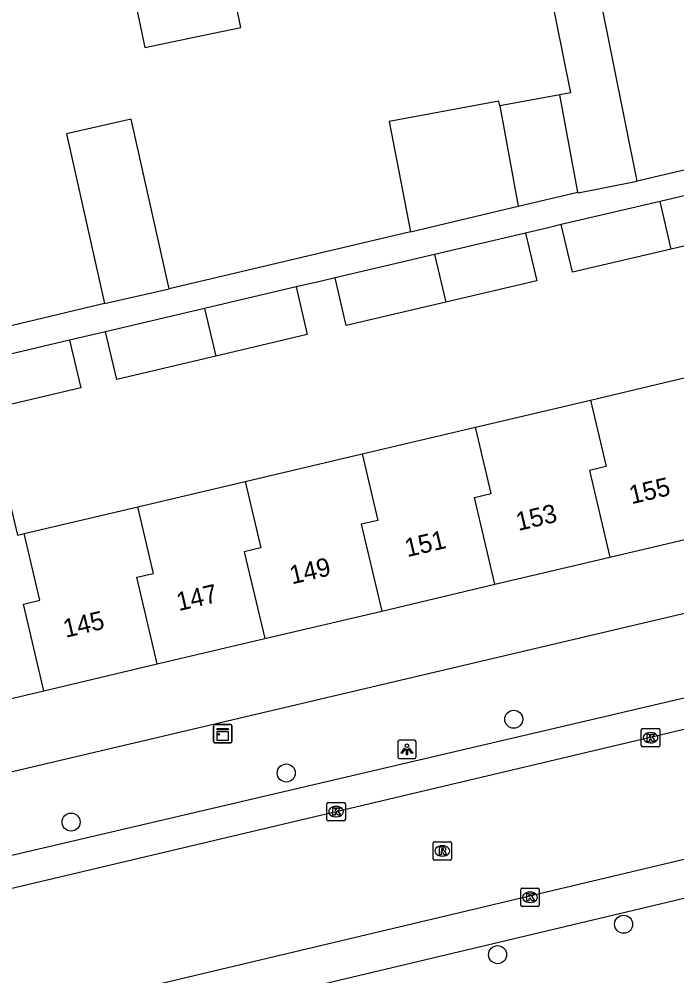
# Model space of a CAD drawing. Extents: x 162990 to 165007, y 383433 to 384336.
# Drawn here: x 164173.2 to 164208.8, y 384114.3 to 384166.2 of the extents above; entities that cross this region are included whole.
import ezdxf

# ---------------------------------------------------------------- set-up
doc = ezdxf.new("R2010")
doc.units = 0
for name, color, linetype in [('IMGEO_Boom', 7, 'Continuous'), ('IMGEO_Kast', 7, 'Continuous'), ('IMGEO_Kolk', 7, 'Continuous'), ('IMGEO_Lichtpunt', 7, 'Continuous'), ('IMGEO_Pand', 7, 'Continuous'), ('IMGEO_Pand_nummerreeks', 7, 'Continuous'), ('IMGEO_Rijbaan_lokaal_open', 7, 'Continuous'), ('IMGEO_Rioolput', 7, 'Continuous'), ('IMGEO_Voetpad_open', 7, 'Continuous')]:
    doc.layers.add(name, color=color, linetype=linetype)

msp = doc.modelspace()

# ---------------------------------------------------------------- linework, layer by layer
at = {"layer": 'IMGEO_Boom'}
for centre in [(164199.955, 384128.23), (164187.625, 384125.313), (164175.968, 384122.65), (164205.906, 384117.115), (164199.074, 384115.466)]:
    msp.add_circle(centre, 0.489, dxfattribs=at)
at = {"layer": 'IMGEO_Kast'}
for p, q in [((164183.687, 384127.02), (164183.687, 384127.861)), ((164183.687, 384127.861), (164183.687, 384127.02)), ((164183.762, 384127.945), (164184.603, 384127.945)), ((164184.603, 384127.945), (164183.762, 384127.945)), ((164184.687, 384127.87), (164184.687, 384127.029)), ((164184.687, 384127.029), (164184.687, 384127.87)), ((164184.612, 384126.945), (164183.771, 384126.945)), ((164183.771, 384126.945), (164184.612, 384126.945))]:
    msp.add_line(p, q, dxfattribs=at)
for points in [[(164183.882, 384127.735), (164184.482, 384127.735), (164184.482, 384127.65), (164183.882, 384127.65), (164183.882, 384127.735)], [(164183.882, 384127.56), (164184.482, 384127.56), (164184.482, 384127.071), (164183.882, 384127.071), (164183.882, 384127.56)]]:
    msp.add_lwpolyline(points, dxfattribs=at)
msp.add_circle((164183.966, 384127.409), 0.0377, dxfattribs=at)
for centre, start, end in [((164183.765, 384127.867), 92.4484, 184.2845), ((164183.765, 384127.867), 92.4484, 184.2845), ((164184.609, 384127.867), 2.4484, 94.2845), ((164184.609, 384127.867), 2.4484, 94.2845), ((164183.765, 384127.023), 182.4484, 274.2845), ((164183.765, 384127.023), 182.4484, 274.2845), ((164184.609, 384127.023), 272.4484, 4.2845), ((164184.609, 384127.023), 272.4484, 4.2845)]:
    msp.add_arc(centre, 0.0779, start, end, dxfattribs=at)
at = {"layer": 'IMGEO_Kolk'}
for p, q in [((164206.938, 384127.728), (164207.79, 384127.728)), ((164206.863, 384126.802), (164206.863, 384127.654)), ((164207.351, 384127.508), (164207.376, 384127.508)), ((164207.864, 384127.654), (164207.864, 384126.802)), ((164207.79, 384126.728), (164206.938, 384126.728)), ((164207.374, 384126.948), (164207.349, 384126.948)), ((164189.828, 384122.795), (164189.828, 384123.647)), ((164189.903, 384123.721), (164190.755, 384123.721)), ((164190.829, 384123.647), (164190.829, 384122.795)), ((164190.316, 384123.501), (164190.341, 384123.501)), ((164190.755, 384122.721), (164189.903, 384122.721)), ((164190.339, 384122.941), (164190.314, 384122.941)), ((164200.335, 384118.15), (164200.335, 384119.002)), ((164200.41, 384119.076), (164201.262, 384119.076)), ((164201.336, 384119.002), (164201.336, 384118.15)), ((164200.823, 384118.856), (164200.848, 384118.856)), ((164201.262, 384118.076), (164200.41, 384118.076)), ((164200.846, 384118.296), (164200.821, 384118.296))]:
    msp.add_line(p, q, dxfattribs=at)
for points in [[(164206.938, 384127.728), (164207.79, 384127.728)], [(164206.863, 384126.802), (164206.863, 384127.654)], [(164207.184, 384127.428), (164207.307, 384127.428), (164207.307, 384127.277), (164207.437, 384127.428), (164207.601, 384127.428), (164207.455, 384127.277), (164207.608, 384127.028), (164207.456, 384127.028), (164207.371, 384127.192), (164207.307, 384127.125), (164207.307, 384127.028), (164207.184, 384127.028), (164207.184, 384127.428)], [(164207.864, 384127.654), (164207.864, 384126.802)], [(164207.79, 384126.728), (164206.938, 384126.728)], [(164189.828, 384122.795), (164189.828, 384123.647)], [(164189.903, 384123.721), (164190.755, 384123.721)], [(164190.829, 384123.647), (164190.829, 384122.795)], [(164190.149, 384123.421), (164190.272, 384123.421), (164190.272, 384123.27), (164190.402, 384123.421), (164190.566, 384123.421), (164190.42, 384123.27), (164190.573, 384123.021), (164190.421, 384123.021), (164190.336, 384123.185), (164190.272, 384123.118), (164190.272, 384123.021), (164190.149, 384123.021), (164190.149, 384123.421)], [(164190.755, 384122.721), (164189.903, 384122.721)], [(164200.335, 384118.15), (164200.335, 384119.002)], [(164200.41, 384119.076), (164201.262, 384119.076)], [(164201.336, 384119.002), (164201.336, 384118.15)], [(164200.656, 384118.776), (164200.779, 384118.776), (164200.779, 384118.625), (164200.909, 384118.776), (164201.073, 384118.776), (164200.927, 384118.625), (164201.08, 384118.376), (164200.928, 384118.376), (164200.843, 384118.54), (164200.779, 384118.473), (164200.779, 384118.376), (164200.656, 384118.376), (164200.656, 384118.776)], [(164201.262, 384118.076), (164200.41, 384118.076)]]:
    msp.add_lwpolyline(points, dxfattribs=at)
for centre, start, end in [((164206.94, 384127.652), 91.552, 178.448), ((164206.94, 384127.652), 91.552, 178.448), ((164207.788, 384127.652), 1.552, 88.448), ((164207.788, 384127.652), 1.552, 88.448), ((164206.94, 384126.804), 181.552, 268.448), ((164206.94, 384126.804), 181.552, 268.448), ((164207.788, 384126.804), 271.552, 358.448), ((164207.788, 384126.804), 271.552, 358.448), ((164189.905, 384123.645), 91.552, 178.448), ((164189.905, 384123.645), 91.552, 178.448), ((164190.753, 384123.645), 1.552, 88.448), ((164190.753, 384123.645), 1.552, 88.448), ((164189.905, 384122.797), 181.552, 268.448), ((164189.905, 384122.797), 181.552, 268.448), ((164190.753, 384122.797), 271.552, 358.448), ((164190.753, 384122.797), 271.552, 358.448), ((164200.412, 384119), 91.552, 178.448), ((164200.412, 384119), 91.552, 178.448), ((164201.26, 384119), 1.552, 88.448), ((164201.26, 384119), 1.552, 88.448), ((164200.412, 384118.152), 181.552, 268.448), ((164200.412, 384118.152), 181.552, 268.448), ((164201.26, 384118.152), 271.552, 358.448), ((164201.26, 384118.152), 271.552, 358.448)]:
    msp.add_arc(centre, 0.0765, start, end, dxfattribs=at)
for centre, major_axis, ratio, start_param, end_param in [((164207.35, 384127.228), (-0.387, 0.002), 0.722429, 4.712389, 7.853982), ((164207.375, 384127.228), (-0.39, 0.002), 0.717154, 1.570796, 4.712389), ((164190.315, 384123.221), (-0.387, 0.002), 0.722429, 4.712389, 7.853982), ((164190.34, 384123.221), (-0.39, 0.002), 0.717154, 1.570796, 4.712389), ((164200.822, 384118.576), (-0.387, 0.002), 0.722429, 4.712389, 7.853982), ((164200.847, 384118.576), (-0.39, 0.002), 0.717154, 1.570796, 4.712389)]:
    msp.add_ellipse(centre, major_axis=major_axis, ratio=ratio, start_param=start_param, end_param=end_param, dxfattribs=at)
at = {"layer": 'IMGEO_Lichtpunt'}
for p, q in [((164193.667, 384126.997), (164193.667, 384126.19)), ((164193.667, 384126.997), (164193.667, 384126.19)), ((164194.569, 384127.092), (164193.761, 384127.092)), ((164194.569, 384127.092), (164193.761, 384127.092)), ((164194.663, 384126.19), (164194.663, 384126.997)), ((164194.663, 384126.19), (164194.663, 384126.997)), ((164193.761, 384126.096), (164194.569, 384126.096)), ((164193.761, 384126.096), (164194.569, 384126.096))]:
    msp.add_line(p, q, dxfattribs=at)
for points in [[(164194.041, 384126.661), (164194.08, 384126.633), (164193.892, 384126.371), (164193.854, 384126.398), (164194.041, 384126.661)], [(164194.143, 384126.613), (164194.19, 384126.613), (164194.19, 384126.291), (164194.143, 384126.291), (164194.143, 384126.613)], [(164194.253, 384126.633), (164194.291, 384126.66), (164194.478, 384126.398), (164194.439, 384126.37), (164194.253, 384126.633)]]:
    msp.add_lwpolyline(points, dxfattribs=at)
msp.add_circle((164194.166, 384126.795), 0.0994, dxfattribs=at)
for centre, start, end in [((164193.761, 384126.997), 90, 180), ((164193.761, 384126.997), 90, 180), ((164194.569, 384126.997), 0, 90), ((164194.569, 384126.997), 0, 90), ((164193.761, 384126.19), 180, 270), ((164193.761, 384126.19), 180, 270), ((164194.569, 384126.19), 270, 0), ((164194.569, 384126.19), 270, 360)]:
    msp.add_arc(centre, 0.0946, start, end, dxfattribs=at)
at = {"layer": 'IMGEO_Pand'}
for points in [[(164201.106, 384185.001), (164195.995, 384183.977), (164196.985, 384179.036), (164197.585, 384176.041), (164198.091, 384173.514), (164200.646, 384174.026), (164203.02, 384162.177), (164202.452, 384162.075)], [(164182.328, 384181.135), (164176.758, 384179.971), (164177.779, 384175.085), (164179.963, 384164.637), (164182.634, 384165.195), (164185.174, 384165.726), (164183.705, 384172.761), (164184.065, 384172.836)], [(164206.648, 384157.404), (164202.674, 384177.191)], [(164202.452, 384162.075), (164199.191, 384161.471)], [(164203.429, 384156.8), (164202.452, 384162.075)], [(164199.191, 384161.471), (164199.142, 384161.734), (164193.206, 384160.635), (164194.351, 384154.652)], [(164199.191, 384161.471), (164200.197, 384156.035)], [(164181.285, 384151.559), (164179.217, 384160.75), (164175.714, 384159.962), (164177.782, 384150.771)], [(164203.429, 384156.8), (164203.437, 384156.759), (164206.648, 384157.404)], [(164212.836, 384157.462), (164207.879, 384156.297)], [(164212.836, 384157.462), (164213.445, 384154.881), (164208.488, 384153.716)], [(164200.197, 384156.035), (164203.429, 384156.8)], [(164207.879, 384156.297), (164202.527, 384155.039)], [(164208.488, 384153.716), (164207.879, 384156.297)], [(164194.351, 384154.652), (164200.197, 384156.035)], [(164208.488, 384153.716), (164203.136, 384152.457), (164202.527, 384155.039)], [(164200.59, 384154.583), (164195.667, 384153.425)], [(164200.59, 384154.583), (164201.199, 384152.001), (164196.276, 384150.844)], [(164195.667, 384153.425), (164190.271, 384152.157)], [(164195.667, 384153.425), (164196.276, 384150.844)], [(164196.276, 384150.844), (164190.88, 384149.575), (164190.271, 384152.157)], [(164188.159, 384151.661), (164183.195, 384150.493)], [(164188.159, 384151.661), (164188.768, 384149.079), (164183.804, 384147.912)], [(164177.782, 384150.771), (164181.285, 384151.559)], [(164183.195, 384150.493), (164177.84, 384149.234)], [(164183.195, 384150.493), (164183.804, 384147.912)], [(164183.804, 384147.912), (164178.449, 384146.652), (164177.84, 384149.234)], [(164175.893, 384148.776), (164171.219, 384147.677)], [(164175.893, 384148.776), (164176.502, 384146.195), (164171.828, 384145.096)], [(164204.106, 384145.533), (164210.085, 384146.945)], [(164197.876, 384144.061), (164204.106, 384145.533)], [(164204.106, 384145.533), (164204.956, 384141.93), (164204.056, 384141.715), (164205.166, 384137.016)], [(164191.741, 384142.612), (164197.876, 384144.061)], [(164198.936, 384135.544), (164197.826, 384140.243), (164198.726, 384140.458), (164197.876, 384144.061)], [(164185.405, 384141.116), (164191.741, 384142.612)], [(164191.741, 384142.612), (164192.591, 384139.009), (164191.691, 384138.794), (164192.801, 384134.095)], [(164166.531, 384139.45), (164166.36, 384140.175), (164172.272, 384141.571), (164173.067, 384138.201), (164173.434, 384138.288)], [(164179.581, 384139.74), (164185.405, 384141.116)], [(164185.405, 384141.116), (164186.254, 384137.513), (164185.354, 384137.298), (164186.464, 384132.598)], [(164173.434, 384138.288), (164179.581, 384139.74)], [(164180.641, 384131.223), (164179.531, 384135.922), (164180.431, 384136.137), (164179.581, 384139.74)], [(164174.494, 384129.771), (164173.384, 384134.47), (164174.284, 384134.685), (164173.434, 384138.288)], [(164205.166, 384137.016), (164211.145, 384138.428)], [(164198.936, 384135.544), (164205.166, 384137.016)], [(164192.801, 384134.095), (164198.936, 384135.544)], [(164186.464, 384132.598), (164192.801, 384134.095)], [(164180.641, 384131.223), (164186.464, 384132.598)], [(164174.494, 384129.771), (164180.641, 384131.223)], [(164168.215, 384128.288), (164174.494, 384129.771)]]:
    msp.add_lwpolyline(points, dxfattribs=at)
at = {"layer": 'IMGEO_Rijbaan_lokaal_open'}
for points in [[(164152.758, 384114.345), (164212.318, 384128.435)], [(164213.897, 384121.749), (164153.186, 384107.334), (164148.372, 384106.191)]]:
    msp.add_lwpolyline(points, dxfattribs=at)
at = {"layer": 'IMGEO_Rioolput'}
for p, q in [((164195.582, 384120.665), (164195.582, 384121.517)), ((164195.657, 384121.591), (164196.509, 384121.591)), ((164196.583, 384121.517), (164196.583, 384120.665)), ((164196.07, 384121.371), (164196.095, 384121.371)), ((164196.509, 384120.591), (164195.657, 384120.591)), ((164196.093, 384120.811), (164196.068, 384120.811))]:
    msp.add_line(p, q, dxfattribs=at)
for points in [[(164195.582, 384120.665), (164195.582, 384121.517)], [(164195.657, 384121.591), (164196.509, 384121.591)], [(164196.583, 384121.517), (164196.583, 384120.665)], [(164196.171, 384121.289), (164195.919, 384121.291), (164195.919, 384120.891)], [(164195.919, 384120.891), (164196.043, 384120.891), (164196.043, 384121.053), (164196.054, 384121.053)], [(164196.097, 384121.21), (164196.043, 384121.21), (164196.043, 384121.129)], [(164196.043, 384121.129), (164196.095, 384121.129)], [(164196.101, 384121.024), (164196.172, 384120.891), (164196.312, 384120.891), (164196.247, 384121.017)], [(164196.509, 384120.591), (164195.657, 384120.591)]]:
    msp.add_lwpolyline(points, dxfattribs=at)
for centre, radius, start, end in [((164195.659, 384121.515), 0.0765, 91.552, 178.448), ((164195.659, 384121.515), 0.0765, 91.552, 178.448), ((164196.507, 384121.515), 0.0765, 1.552, 88.448), ((164196.507, 384121.515), 0.0765, 1.552, 88.448), ((164196.053, 384121), 0.0533, 26.0293, 88.6989), ((164196.079, 384121.318), 0.19, 274.7715, 282.9687), ((164196.103, 384121.114), 0.0964, 77.0061, 93.1865), ((164196.117, 384121.171), 0.0378, 276.6634, 79.6772), ((164196.17, 384121.179), 0.109, 350.3612, 89.416), ((164196.168, 384121.179), 0.112, 277.5842, 350.9817), ((164196.152, 384120.964), 0.108, 29.5134, 73.7905), ((164195.659, 384120.667), 0.0765, 181.552, 268.448), ((164195.659, 384120.667), 0.0765, 181.552, 268.448), ((164196.507, 384120.667), 0.0765, 271.552, 358.448), ((164196.507, 384120.667), 0.0765, 271.552, 358.448)]:
    msp.add_arc(centre, radius, start, end, dxfattribs=at)
for centre, major_axis, ratio, start_param, end_param in [((164196.069, 384121.091), (-0.387, 0.002), 0.722429, 4.712389, 7.853982), ((164196.094, 384121.091), (-0.39, 0.002), 0.717154, 1.570796, 4.712389)]:
    msp.add_ellipse(centre, major_axis=major_axis, ratio=ratio, start_param=start_param, end_param=end_param, dxfattribs=at)
at = {"layer": 'IMGEO_Voetpad_open'}
for points in [[(164219.641, 384160.448), (164206.648, 384157.404)], [(164202.527, 384155.039), (164201.898, 384154.891), (164200.59, 384154.583)], [(164194.351, 384154.652), (164181.285, 384151.559)], [(164190.271, 384152.157), (164189.53, 384151.983), (164188.159, 384151.661)], [(164177.782, 384150.771), (164165.299, 384147.775)], [(164177.84, 384149.234), (164177.367, 384149.123), (164175.893, 384148.776)], [(164149.697, 384119.951), (164236.651, 384140.453)], [(164243.757, 384137.462), (164154.918, 384116.675)], [(164214.8, 384119.856), (164157.009, 384106.119), (164144.005, 384103.025), (164111.601, 384095.448), (164083.09, 384088.781)]]:
    msp.add_lwpolyline(points, dxfattribs=at)

# ---------------------------------------------------------------- texts
at = {"layer": 'IMGEO_Pand_nummerreeks'}
for s, p in [('155', (164206.332, 384139.88)), ('153', (164200.2, 384138.432)), ('151', (164194.179, 384137.009)), ('149', (164187.937, 384135.535)), ('147', (164181.805, 384134.087)), ('145', (164175.673, 384132.638))]:
    msp.add_text(s, height=1, rotation=13.2898, dxfattribs=at).set_placement(p)

doc.saveas('drawing.dxf')
